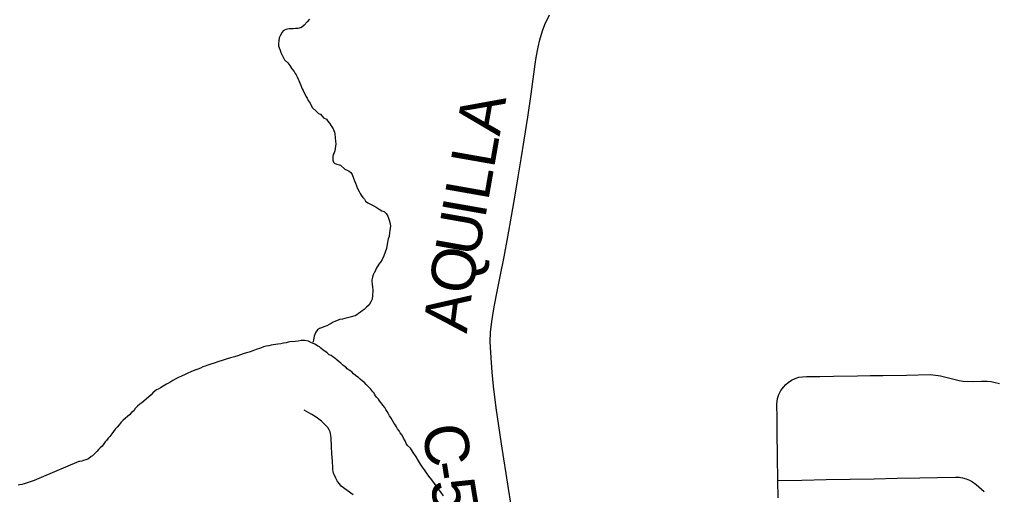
# Model space of a CAD drawing. Extents: x 103424 to 290657, y 38711 to 110967.
# Drawn here: x 149253 to 155965, y 61660 to 64911 of the extents above; entities that cross this region are included whole.
import ezdxf

# ---------------------------------------------------------------- set-up
doc = ezdxf.new("R2010")
doc.units = 0
for name, color, linetype in [('GM_X_County_Road', 7, 'Continuous'), ('GM_X_County_Road_Text', 7, 'Continuous'), ('GM_X_Minor_River', 7, 'Continuous'), ('GM_X_Township_Road', 7, 'Continuous')]:
    doc.layers.add(name, color=color, linetype=linetype)

msp = doc.modelspace()

# ---------------------------------------------------------------- linework, layer by layer
at = {"layer": 'GM_X_County_Road'}
msp.add_lwpolyline([(152619, 61599.8), (152603.2, 61701.7), (152587.4, 61803.7), (152571.2, 61904.8), (152555, 62005.9), (152536.5, 62129.8), (152518.1, 62253.7), (152500.4, 62400.5), (152491.6, 62498.1), (152482.8, 62595.8), (152477.1, 62707.7), (152479.5, 62768), (152487.3, 62843.5), (152504.6, 62944.8), (152526.7, 63060.5), (152546, 63151.5), (152572.4, 63287.3), (152598.9, 63423.1), (152623.9, 63566.2), (152648.9, 63709.4), (152669.7, 63833.5), (152690.4, 63957.5), (152710.5, 64085.9), (152734.2, 64243.2), (152758, 64400.5), (152772.2, 64502.9), (152786.3, 64605.2), (152792.9, 64650.4), (152804.8, 64721.3), (152817.1, 64773), (152836, 64833.3), (152851.9, 64878), (152883.1, 64942.4)], dxfattribs=at)
at = {"layer": 'GM_X_Minor_River'}
for points in [[(151239.1, 64913.5), (151223.4, 64895), (151203.6, 64872.4), (151183.7, 64857.8), (151159.6, 64849.2), (151143.5, 64850.9), (151127.3, 64848.5), (151115.2, 64848.2), (151099.1, 64847.9), (151089, 64845.6), (151078.9, 64843.4), (151068.9, 64839.2), (151058.9, 64834.9), (151051, 64824.6), (151037.4, 64800.1), (151031.7, 64785.8), (151030.1, 64765.6), (151026.4, 64747.4), (151026.8, 64731.2), (151031.1, 64717.2), (151037.5, 64701.2), (151043.9, 64685.2), (151052.4, 64667.2), (151067.2, 64635.2), (151089.9, 64615.5), (151104.4, 64595.6), (151119, 64573.7), (151133.6, 64555.9), (151141.9, 64541.9), (151148.2, 64532), (151154.6, 64518), (151160.9, 64504), (151167.2, 64494), (151171.5, 64482), (151177.9, 64466), (151184.4, 64447.9), (151188.7, 64435.9), (151194.9, 64426), (151214, 64386), (151222.3, 64374.1), (151230.7, 64358.1), (151243.3, 64338.2), (151258.1, 64308.2), (151284.9, 64284.6), (151301.4, 64268.8), (151313.6, 64263), (151334.3, 64239.2), (151354.7, 64229.6)], [(151354.7, 64229.6), (151363.1, 64217.6), (151375.5, 64201.7), (151388.1, 64183.8), (151400.6, 64163.9), (151406.9, 64151.9), (151411.2, 64139.9), (151413.5, 64127.9), (151416.1, 64101.7), (151416.5, 64079.5), (151419, 64059.3), (151415.6, 64029), (151411.9, 64012.7), (151408.2, 63998.5), (151402.4, 63986.3), (151398.6, 63972.1), (151399.2, 63947.8), (151403.4, 63935.8), (151413.8, 63926), (151426, 63922.2), (151442.2, 63916.5), (151452.4, 63914.7), (151481.3, 63887), (151497.6, 63879.3), (151511.9, 63873.6), (151522.2, 63863.7), (151530.6, 63849.7), (151541.2, 63825.8), (151547.6, 63807.7), (151554, 63791.7), (151560.5, 63773.7), (151569, 63753.7), (151579.5, 63733.7), (151585.9, 63719.7), (151594.2, 63707.8), (151604.6, 63693.9), (151617, 63682), (151623.4, 63668), (151639.8, 63656.3), (151656.2, 63646.5), (151670.4, 63640.8), (151695, 63627.2), (151715.5, 63613.5), (151735.9, 63601.8), (151750.2, 63596.1), (151764.7, 63582.3), (151775.1, 63564.3), (151781.5, 63552.3), (151785.8, 63538.3), (151790.2, 63522.2), (151794.7, 63498.1), (151791, 63483.9), (151789.3, 63467.7), (151787.6, 63453.5), (151784.2, 63425.2), (151778.4, 63408.9), (151776.6, 63398.8), (151772.9, 63384.6), (151771.1, 63374.4), (151767.7, 63344.1), (151758.1, 63319.6), (151748.6, 63293.2), (151737, 63268.7), (151725.2, 63250.3), (151713.4, 63235.9), (151695.8, 63207.2), (151692.1, 63193), (151682.3, 63176.6), (151674.5, 63164.4), (151670.8, 63148.1), (151667.2, 63129.9), (151665.4, 63117.7), (151667.8, 63099.6), (151670.3, 63079.5), (151672.7, 63061.3), (151673, 63045.2), (151671.3, 63031), (151671.5, 63020.9), (151668, 62996.6), (151660.3, 62978.3), (151648.6, 62957.9), (151630.8, 62941.3), (151612.9, 62926.8), (151601, 62916.4), (151589, 62908.1), (151575.1, 62899.7), (151563.2, 62889.4), (151551.2, 62883), (151533.1, 62878.6), (151517, 62874.2), (151498.9, 62869.8), (151480.8, 62865.4), (151464.7, 62861), (151446.7, 62856.6), (151428.6, 62850.1), (151412.6, 62843.7), (151400.5, 62839.4), (151388.6, 62831.1), (151374.6, 62822.7), (151358.6, 62814.3), (151336.5, 62807.7)], [(151336.5, 62807.7), (151322.5, 62801.4), (151308.5, 62797), (151294.5, 62786.6), (151282.8, 62770.2), (151275, 62755.9), (151271.2, 62743.7), (151265.7, 62717.3), (151263.9, 62705.2), (151262, 62703.1)], [(151162.8, 62709), (151140.6, 62706.5), (151104.3, 62703.7), (151094.3, 62701.5), (151080.2, 62697.1), (151062.1, 62694.7), (151041.9, 62690.3), (151021.8, 62687.8), (151005.7, 62685.4), (150991.6, 62683.1), (150977.5, 62680.8), (150961.4, 62678.4), (150943.3, 62674), (150923.2, 62669.5), (150903.1, 62661), (150875, 62652.3), (150850.9, 62643.7), (150826.9, 62635.1), (150806.8, 62628.6), (150784.7, 62622.1), (150766.7, 62615.6), (150748.6, 62609.2), (150724.5, 62602.6), (150698.4, 62596), (150674.3, 62587.4), (150648.2, 62578.7), (150612.1, 62567.8), (150586, 62559.2), (150563.9, 62552.6), (150543.9, 62544.1), (150525.8, 62537.7), (150509.7, 62533.3), (150493.7, 62524.9), (150473.7, 62518.4), (150453.6, 62509.9), (150427.6, 62499.2), (150405.6, 62490.7), (150387.6, 62480.2), (150361.5, 62469.5), (150341.5, 62461), (150323.5, 62450.5), (150303.6, 62440), (150281.6, 62427.4), (150259.6, 62414.8), (150237.7, 62402.2), (150219.7, 62389.7), (150201.7, 62381.2), (150191.8, 62375), (150179.8, 62366.6), (150165.9, 62356.2), (150154.1, 62341.8), (150136.2, 62325.3), (150090.6, 62287.9), (150076.6, 62277.6), (150060.7, 62265.1), (150044.9, 62248.6), (150035.2, 62232.2), (150019.2, 62219.8), (150005.4, 62205.3), (149991.5, 62192.9), (149977.6, 62180.5), (149963.8, 62168.1), (149949.9, 62153.7), (149936.1, 62137.2), (149922.3, 62120.7), (149908.5, 62106.3), (149896.7, 62089.9), (149884.9, 62075.5), (149871.1, 62057), (149859.3, 62044.7), (149849.5, 62030.3), (149839.6, 62020), (149829.8, 62005.7), (149818, 61991.3), (149806.1, 61978.9), (149794.3, 61966.5), (149784.4, 61956.2), (149772.5, 61943.8), (149752.7, 61925.2), (149742.7, 61919), (149724.8, 61904.4), (149706.8, 61896), (149690.7, 61891.6), (149678.7, 61887.3), (149666.6, 61885), (149658.6, 61884.8), (149402.2, 61776.3)], [(152157.5, 61650.5), (152140.8, 61674.3), (152115.9, 61706.1), (152095.1, 61733.9), (152076.3, 61759.7), (152057.6, 61785.6), (152041, 61807.4), (152026.4, 61827.3), (152013.8, 61847.2), (151999.3, 61867.1), (151986.7, 61889), (151969.9, 61916.9), (151949.1, 61946.8), (151930.2, 61976.6), (151911.7, 61994.4), (151901.3, 62008.3), (151894.8, 62026.3), (151884.3, 62046.3), (151873.8, 62066.3), (151861.3, 62082.2), (151852.9, 62096.1), (151842.5, 62108), (151834.2, 62121.9), (151827.8, 62133.9), (151819.5, 62145.9), (151806.9, 62165.8), (151798.5, 62181.7), (151788.1, 62197.7), (151779.7, 62211.6), (151771.3, 62227.6), (151762.9, 62241.5), (151754.5, 62255.5), (151744.1, 62269.4), (151719.2, 62301.2), (151712.9, 62313.1), (151698.4, 62327), (151688, 62342.9), (151681.7, 62352.8), (151673.4, 62362.8), (151658.9, 62380.6), (151644.4, 62396.5), (151627.9, 62412.2), (151613.4, 62428.1), (151603.1, 62435.9), (151586.7, 62449.7), (151574.3, 62459.6), (151564.1, 62467.4), (151553.8, 62475.2), (151541.5, 62485.1), (151529, 62498.9), (151510.6, 62510.6), (151498.3, 62520.5), (151488, 62530.4), (151477.7, 62538.2), (151465.3, 62548), (151455, 62557.9), (151442.7, 62567.7), (151428.3, 62579.5), (151413.9, 62593.4), (151399.5, 62601.1), (151387.2, 62610.9), (151375, 62616.7), (151360.6, 62628.5), (151350.3, 62636.4), (151333.9, 62648.1), (151317.4, 62661.9), (151307.1, 62669.8), (151296.9, 62675.6), (151280.5, 62687.4), (151270.3, 62691.2), (151254, 62696.9), (151233.6, 62708.6), (151207.2, 62714), (151182.9, 62713.5), (151162.8, 62709)], [(149402.2, 61776.3), (149354.1, 61755), (149326, 61746.3), (149306, 61739.9), (149283.9, 61733.3), (149267.8, 61728.9), (149253.7, 61726.6), (149243.6, 61724.4)]]:
    msp.add_lwpolyline(points, dxfattribs=at)
at = {"layer": 'GM_X_Township_Road'}
for points in [[(154450.3, 61637.5), (154447.5, 61755.2), (154445.3, 61920.3), (154443.1, 62085.3), (154441.9, 62181.9), (154440.6, 62278.5), (154445.2, 62315.7), (154455.2, 62345), (154468.1, 62371.3), (154485.6, 62394.7), (154501.7, 62412.6), (154518.7, 62426.9), (154541.7, 62442), (154565.5, 62454), (154591.7, 62461.8), (154617, 62465.9), (154644.1, 62466.4), (154736, 62468), (154827.9, 62469.6), (154992.9, 62472.1), (155079.5, 62473.3), (155166.2, 62474.6), (155328.5, 62477.6), (155490.7, 62480.6), (155545.9, 62475.1), (155561.6, 62471.2)], [(155561.6, 62471.2), (155661.2, 62446.6), (155690.1, 62440.2), (155717.7, 62436.5), (155781.9, 62434.2), (155843.5, 62435), (155881.4, 62435.6), (155908.6, 62432.2), (155928, 62428.8), (155965.3, 62419.3)], [(151539.6, 61656.5), (151457.1, 61717.4), (151443.8, 61732.1), (151431.1, 61747.8), (151419.8, 61770.8), (151408, 61796.8), (151404.7, 61806.5), (151401.2, 61816.9), (151399.2, 61830.1), (151398.5, 61841.9), (151396, 61888.5), (151393.3, 61937.5), (151390.7, 61987), (151387.6, 62044.7), (151386, 62063.9), (151384, 62076.2), (151380.6, 62088.4), (151373.2, 62103.2), (151363.9, 62117.4), (151350.1, 62132.5), (151335.5, 62147.8), (151320.8, 62161.5), (151304.1, 62174.7), (151285, 62188.9), (151255.1, 62208), (151234.5, 62219.3), (151202.6, 62236.9)], [(154447.5, 61755.2), (154612.5, 61758.4), (154777.5, 61761.5), (154942.6, 61764.7), (155107.6, 61767.8), (155263.9, 61770.8), (155420.2, 61773.8), (155542, 61775.7), (155663.9, 61777.6), (155688.8, 61777.1), (155713.5, 61773.5), (155737.4, 61767), (155760.3, 61757.5), (155781.9, 61745.3), (155805.4, 61728), (155860.9, 61679.5)]]:
    msp.add_lwpolyline(points, dxfattribs=at)

# ---------------------------------------------------------------- texts
at = {"layer": 'GM_X_County_Road_Text'}
for s, rotation, p in [('A', 80.02375, (152541.5, 64108.4)), ('L', 80.02333, (152502.4, 63886)), ('L', 80.02333, (152463.2, 63663.6)), ('I', 80.0205, (152441.8, 63541.5)), ('U', 80.03042, (152395.8, 63279.9)), ('Q', 80.04181, (152349.8, 63018.2)), ('A', 82.66533, (152316.5, 62758.4)), ('C', 277.54281, (152012.2, 62124.6)), ('-', 279.10719, (152046.1, 61869.9)), ('5', 279.26634, (152065.8, 61746.6))]:
    msp.add_text(s, height=301.9, rotation=rotation, dxfattribs=at).set_placement(p)

doc.saveas('drawing.dxf')
